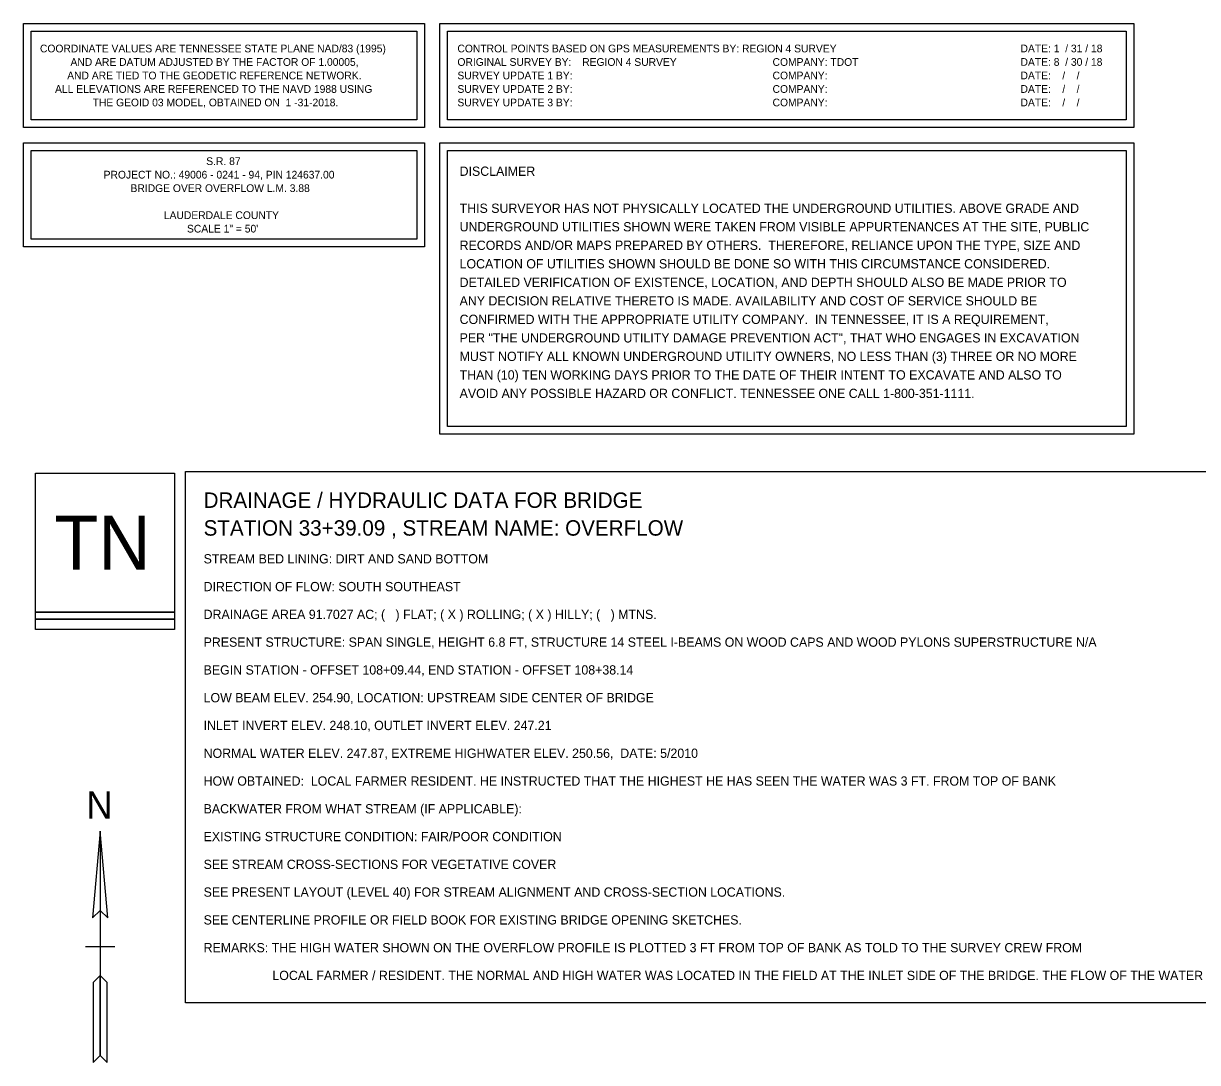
# Model space of a CAD drawing. Extents: x 818717 to 846077, y 440014 to 541392.
# Drawn here: x 830103 to 830865, y 497860 to 498533 of the extents above; entities that cross this region are included whole.
import ezdxf

# ---------------------------------------------------------------- set-up
doc = ezdxf.new("R2010")
doc.units = 0
for name, color, linetype in [('DESIGN - SCRATCH - User 1', 7, 'Continuous'), ('SURVEY - CENTERLINE - Preliminary', 7, 'Continuous'), ('SURVEY - CONTROL with Text', 7, 'Continuous'), ('SURVEY - PROFILE - Drainage - Bridge Hydraulic Data with Text', 7, 'Continuous'), ('SURVEY - PROJECT INFORMATION and NOTES', 7, 'Continuous'), ('SURVEY - UTILITIES - Owners', 7, 'Continuous')]:
    doc.layers.add(name, color=color, linetype=linetype)

msp = doc.modelspace()

# ---------------------------------------------------------------- linework, layer by layer
at = {"layer": 'DESIGN - SCRATCH - User 1'}
msp.add_lwpolyline([(830208.24, 498242.49), (831292.88, 498242.49), (831292.88, 497898.09), (830208.24, 497898.09)], close=True, dxfattribs=at)
at = {"layer": 'SURVEY - CENTERLINE - Preliminary'}
for points in [[(830111.08, 498241.41), (830201.08, 498241.41), (830201.08, 498151.41), (830111.08, 498151.41)], [(830111.08, 498241.41), (830201.08, 498241.41), (830201.08, 498151.41), (830111.08, 498151.41)], [(830111.08, 498151.41), (830201.08, 498151.41), (830201.08, 498146.91), (830111.08, 498146.91)], [(830111.08, 498151.41), (830201.08, 498151.41), (830201.08, 498146.91), (830111.08, 498146.91)], [(830111.08, 498146.91), (830201.08, 498146.91), (830201.08, 498140.16), (830111.08, 498140.16)], [(830111.08, 498146.91), (830201.08, 498146.91), (830201.08, 498140.16), (830111.08, 498140.16)]]:
    msp.add_lwpolyline(points, close=True, dxfattribs=at)
at = {"layer": 'SURVEY - CONTROL with Text'}
for points in [[(830103.24, 498465.47), (830103.24, 498532.87), (830363.24, 498532.87), (830363.24, 498465.47)], [(830108.24, 498470.47), (830108.24, 498527.87), (830358.24, 498527.87), (830358.24, 498470.47)], [(830373.24, 498465.47), (830373.24, 498532.87), (830823.24, 498532.87), (830823.24, 498465.47)], [(830378.24, 498470.47), (830378.24, 498527.87), (830818.24, 498527.87), (830818.24, 498470.47)]]:
    msp.add_lwpolyline(points, close=True, dxfattribs=at)
at = {"layer": 'SURVEY - PROJECT INFORMATION and NOTES'}
for p, q in [((830152.95, 497934.52), (830143.5, 497934.52)), ((830162.4, 497934.52), (830152.95, 497934.52))]:
    msp.add_line(p, q, dxfattribs=at)
for points in [[(830103.24, 498388.08), (830103.24, 498455.47), (830363.24, 498455.47), (830363.24, 498388.08)], [(830108.24, 498393.08), (830108.24, 498450.47), (830358.24, 498450.47), (830358.24, 498393.08)], [(830152.95, 497958.12), (830157.85, 497953.22), (830152.95, 498009.52)], [(830148.4, 497859.52), (830152.95, 497864.07), (830152.95, 497915.82), (830148.4, 497911.27)]]:
    msp.add_lwpolyline(points, close=True, dxfattribs=at)
msp.add_lwpolyline([(830152.95, 498009.52), (830148.05, 497953.22), (830152.95, 497958.12), (830157.85, 497953.22), (830152.95, 498009.52), (830152.95, 497864.07), (830157.5, 497859.52), (830157.5, 497911.27), (830152.95, 497915.82), (830148.4, 497911.27), (830148.4, 497859.52), (830152.95, 497864.07)], dxfattribs=at)
at = {"layer": 'SURVEY - UTILITIES - Owners'}
for points in [[(830373.24, 498266.68), (830373.24, 498455.47), (830823.24, 498455.47), (830823.24, 498266.68)], [(830378.24, 498271.68), (830378.24, 498450.47), (830818.24, 498450.47), (830818.24, 498271.68)]]:
    msp.add_lwpolyline(points, close=True, dxfattribs=at)

# ---------------------------------------------------------------- texts
at = {"layer": 'SURVEY - CENTERLINE - Preliminary'}
msp.add_text('TN', height=35.002, dxfattribs=at).set_placement((830123.23, 498178.91))
at = {"layer": 'SURVEY - CONTROL with Text'}
for s, p in [('COORDINATE VALUES ARE TENNESSEE STATE PLANE NAD/83 (1995) ', (830113.92, 498514.16)), ('CONTROL POINTS BASED ON GPS MEASUREMENTS BY: REGION 4 SURVEY                            ', (830384.66, 498514.16)), ('DATE: 1  / 31 / 18', (830749.83, 498514.18)), ('AND ARE DATUM ADJUSTED BY THE FACTOR OF 1.00005, ', (830133.72, 498505.42)), ('ORIGINAL SURVEY BY:  ', (830384.66, 498505.42)), ('REGION 4 SURVEY                ', (830465.58, 498505.42)), ('COMPANY: TDOT', (830589.03, 498505.42)), ('DATE: 8  / 30 / 18', (830749.83, 498505.43)), ('AND ARE TIED TO THE GEODETIC REFERENCE NETWORK.  ', (830131.58, 498496.67)), ('SURVEY UPDATE 1 BY: ', (830384.66, 498496.67)), ('COMPANY:                               ', (830589.03, 498496.67)), ('DATE:    /    /   ', (830749.83, 498496.68)), ('ALL ELEVATIONS ARE REFERENCED TO THE NAVD 1988 USING', (830123.72, 498487.92)), ('SURVEY UPDATE 2 BY: ', (830384.66, 498487.92)), ('COMPANY:                               ', (830589.03, 498487.92)), ('DATE:    /    /   ', (830749.83, 498487.93)), ('THE GEOID 03 MODEL, OBTAINED ON  1 -31-2018.', (830148.07, 498479.18)), ('SURVEY UPDATE 3 BY: ', (830384.66, 498479.18)), ('COMPANY:                               ', (830589.03, 498479.18)), ('DATE:    /    /   ', (830749.83, 498479.18))]:
    msp.add_text(s, height=4.998, dxfattribs=at).set_placement(p)
at = {"layer": 'SURVEY - PROFILE - Drainage - Bridge Hydraulic Data with Text'}
for s, height, p in [('DRAINAGE / HYDRAULIC DATA FOR BRIDGE', 10, (830220.06, 498218.95)), ('STATION 33+39.09 , STREAM NAME: OVERFLOW', 10, (830220.06, 498200.95)), ('STREAM BED LINING: DIRT AND SAND BOTTOM', 6, (830220.06, 498182.95)), ('DIRECTION OF FLOW: SOUTH SOUTHEAST ', 6, (830220.06, 498164.95)), ('DRAINAGE AREA 91.7027 AC; (   ) FLAT; ( X ) ROLLING; ( X ) HILLY; (   ) MTNS.', 6, (830220.06, 498146.95)), ('PRESENT STRUCTURE: SPAN SINGLE, HEIGHT 6.8 FT, STRUCTURE 14 STEEL I-BEAMS ON WOOD CAPS AND WOOD PYLONS SUPERSTRUCTURE N/A', 6, (830220.06, 498128.95)), ('BEGIN STATION - OFFSET 108+09.44, END STATION - OFFSET 108+38.14', 6, (830220.06, 498110.95)), ('LOW BEAM ELEV. 254.90, LOCATION: UPSTREAM SIDE CENTER OF BRIDGE', 6, (830220.06, 498092.95)), ('INLET INVERT ELEV. 248.10, OUTLET INVERT ELEV. 247.21', 6, (830220.06, 498074.95)), ('NORMAL WATER ELEV. 247.87, EXTREME HIGHWATER ELEV. 250.56,  DATE: 5/2010', 6, (830220.06, 498056.95)), ('HOW OBTAINED:  LOCAL FARMER RESIDENT. HE INSTRUCTED THAT THE HIGHEST HE HAS SEEN THE WATER WAS 3 FT. FROM TOP OF BANK        ', 6, (830220.06, 498038.95)), ('BACKWATER FROM WHAT STREAM (IF APPLICABLE):                                                                             ', 6, (830220.06, 498020.95)), ('EXISTING STRUCTURE CONDITION: FAIR/POOR CONDITION ', 6, (830220.06, 498002.95)), ('SEE STREAM CROSS-SECTIONS FOR VEGETATIVE COVER', 6, (830220.06, 497984.95)), ('SEE PRESENT LAYOUT (LEVEL 40) FOR STREAM ALIGNMENT AND CROSS-SECTION LOCATIONS.', 6, (830220.06, 497966.95)), ('SEE CENTERLINE PROFILE OR FIELD BOOK FOR EXISTING BRIDGE OPENING SKETCHES.', 6, (830220.06, 497948.95)), ('REMARKS: THE HIGH WATER SHOWN ON THE OVERFLOW PROFILE IS PLOTTED 3 FT FROM TOP OF BANK AS TOLD TO THE SURVEY CREW FROM', 6, (830220.06, 497930.95)), ('                    LOCAL FARMER / RESIDENT. THE NORMAL AND HIGH WATER WAS LOCATED IN THE FIELD AT THE INLET SIDE OF THE BRIDGE. THE FLOW OF THE WATER IS DETERMINED FROM THE SLOPE/GRADE OF THE OVERFLOW DITCH HEADING SOUTHEAST', 6, (830220.06, 497912.95))]:
    msp.add_text(s, height=height, dxfattribs=at).set_placement(p)
at = {"layer": 'SURVEY - PROJECT INFORMATION and NOTES'}
for s, height, p in [('S.R. 87', 4.998, (830221.76, 498441.14)), ('PROJECT NO.: 49006 - 0241 - 94, PIN 124637.00', 4.998, (830155.22, 498432.39)), ('BRIDGE OVER OVERFLOW L.M. 3.88', 4.998, (830172.67, 498423.65)), ('LAUDERDALE COUNTY', 4.998, (830194.27, 498406.15)), ('SCALE 1" = 50\'', 4.998, (830209.28, 498397.41)), ('N', 17.72, (830143.9, 498017.57))]:
    msp.add_text(s, height=height, dxfattribs=at).set_placement(p)
at = {"layer": 'SURVEY - UTILITIES - Owners'}
for s, p in [('DISCLAIMER', (830386.07, 498434.14)), ('THIS SURVEYOR HAS NOT PHYSICALLY LOCATED THE UNDERGROUND UTILITIES. ABOVE GRADE AND ', (830386.07, 498410.14)), ('UNDERGROUND UTILITIES SHOWN WERE TAKEN FROM VISIBLE APPURTENANCES AT THE SITE, PUBLIC ', (830386.07, 498398.14)), ('RECORDS AND/OR MAPS PREPARED BY OTHERS.  THEREFORE, RELIANCE UPON THE TYPE, SIZE AND ', (830386.07, 498386.14)), ('LOCATION OF UTILITIES SHOWN SHOULD BE DONE SO WITH THIS CIRCUMSTANCE CONSIDERED.', (830386.07, 498374.14)), ('DETAILED VERIFICATION OF EXISTENCE, LOCATION, AND DEPTH SHOULD ALSO BE MADE PRIOR TO ', (830386.07, 498362.14)), ('ANY DECISION RELATIVE THERETO IS MADE. AVAILABILITY AND COST OF SERVICE SHOULD BE ', (830386.07, 498350.14)), ('CONFIRMED WITH THE APPROPRIATE UTILITY COMPANY.  IN TENNESSEE, IT IS A REQUIREMENT, ', (830386.07, 498338.14)), ('PER "THE UNDERGROUND UTILITY DAMAGE PREVENTION ACT", THAT WHO ENGAGES IN EXCAVATION ', (830386.07, 498326.14)), ('MUST NOTIFY ALL KNOWN UNDERGROUND UTILITY OWNERS, NO LESS THAN (3) THREE OR NO MORE ', (830386.07, 498314.14)), ('THAN (10) TEN WORKING DAYS PRIOR TO THE DATE OF THEIR INTENT TO EXCAVATE AND ALSO TO ', (830386.07, 498302.14)), ('AVOID ANY POSSIBLE HAZARD OR CONFLICT. TENNESSEE ONE CALL 1-800-351-1111.', (830386.07, 498290.14))]:
    msp.add_text(s, height=6, dxfattribs=at).set_placement(p)

doc.saveas('drawing.dxf')
